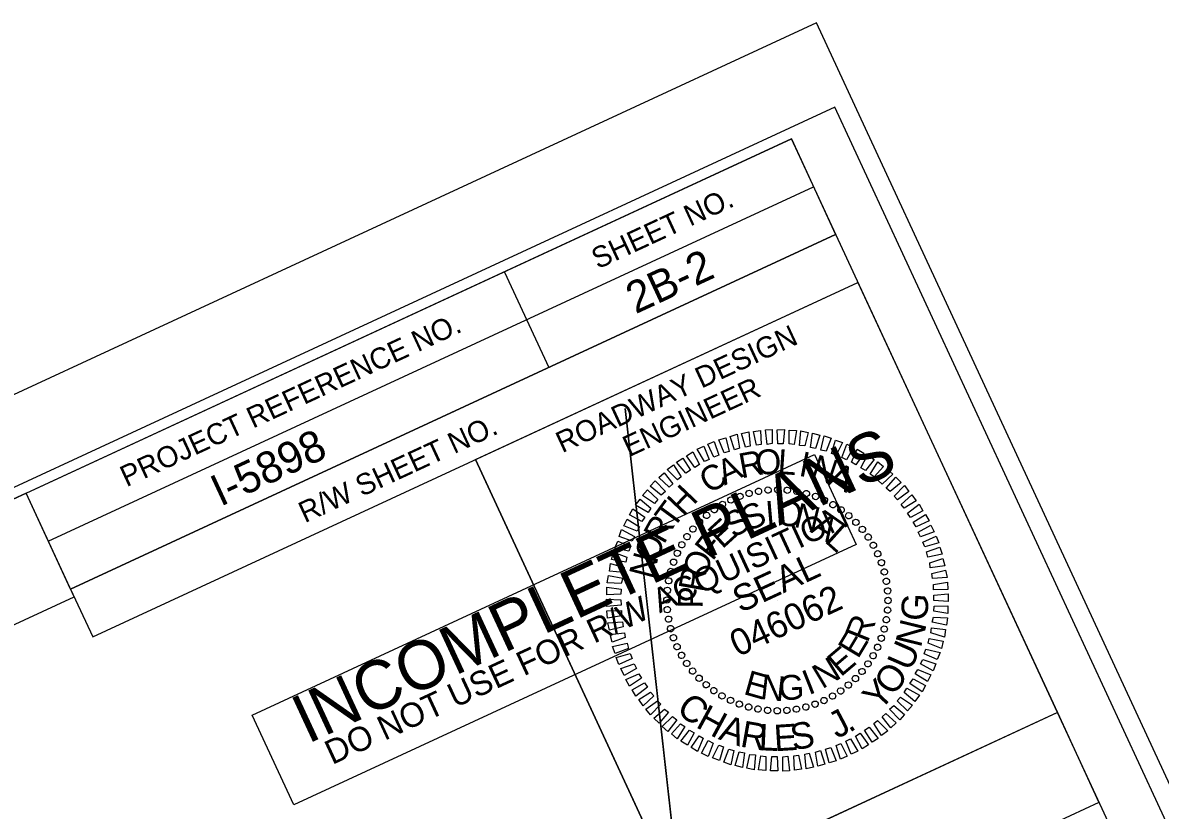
# Model space of a CAD drawing. Extents: x 1722892 to 1724880, y 971019 to 972720.
# Drawn here: x 1724231.4 to 1724501.2, y 972533.3 to 972720.2 of the extents above; entities that cross this region are included whole.
import ezdxf

# ---------------------------------------------------------------- set-up
doc = ezdxf.new("R2010")
doc.units = 0
for name, color, linetype in [('Default', 7, 'Continuous'), ('Old_Level_2', 7, 'Continuous'), ('Prop Dimension Text', 7, 'Continuous'), ('Sheet Data Field CELL', 7, 'Continuous'), ('Sheet Layout Plan Border', 7, 'Continuous'), ('Sheet Plan CELL', 7, 'Continuous'), ('Sheet Plot Border Inside CELL', 7, 'Continuous'), ('Sheet Plot Border Outside CELL', 7, 'Continuous'), ('Sheet Sticker Exception Certification CELL', 7, 'Continuous'), ('Sheet Sticker Incomplete CELL', 7, 'Continuous')]:
    doc.layers.add(name, color=color, linetype=linetype)

msp = doc.modelspace()

# ---------------------------------------------------------------- linework, layer by layer
at = {"layer": 'Old_Level_2'}
for p, q in [((1724401.55, 972607.86), (1724401.55, 972607.86)), ((1724403.73, 972608.52), (1724403.73, 972608.52)), ((1724405.91, 972609.05), (1724405.91, 972609.05)), ((1724408.21, 972609.35), (1724408.21, 972609.35)), ((1724410.5, 972609.42), (1724410.5, 972609.42)), ((1724412.79, 972609.36), (1724412.79, 972609.36)), ((1724415.06, 972609.01), (1724415.06, 972609.01)), ((1724417.32, 972608.54), (1724417.32, 972608.54)), ((1724419.46, 972607.83), (1724419.46, 972607.83)), ((1724395.48, 972604.69), (1724395.48, 972604.69)), ((1724397.36, 972605.95), (1724397.36, 972605.95)), ((1724399.41, 972607), (1724399.41, 972607)), ((1724421.63, 972606.96), (1724421.63, 972606.96)), ((1724423.6, 972605.89), (1724423.6, 972605.89)), ((1724425.55, 972604.62), (1724425.55, 972604.62)), ((1724393.59, 972603.31), (1724393.59, 972603.31)), ((1724427.38, 972603.25), (1724427.38, 972603.25)), ((1724390.37, 972600.12), (1724390.37, 972600.12)), ((1724391.89, 972601.78), (1724391.89, 972601.78)), ((1724429.04, 972601.73), (1724429.04, 972601.73)), ((1724430.57, 972600.03), (1724430.57, 972600.03)), ((1724388.99, 972598.29), (1724388.99, 972598.29)), ((1724431.95, 972598.14), (1724431.95, 972598.14)), ((1724386.65, 972594.37), (1724386.65, 972594.37)), ((1724387.73, 972596.34), (1724387.73, 972596.34)), ((1724433.21, 972596.25), (1724433.21, 972596.25)), ((1724434.26, 972594.2), (1724434.26, 972594.2)), ((1724385.78, 972592.2), (1724385.78, 972592.2)), ((1724435.12, 972592.07), (1724435.12, 972592.07)), ((1724385.08, 972590.06), (1724385.08, 972590.06)), ((1724435.78, 972589.88), (1724435.78, 972589.88)), ((1724384.61, 972587.8), (1724384.61, 972587.8)), ((1724436.31, 972587.7), (1724436.31, 972587.7)), ((1724384.2, 972583.24), (1724384.2, 972583.24)), ((1724384.25, 972585.53), (1724384.25, 972585.53)), ((1724410.44, 972583.18), (1724410.44, 972583.18)), ((1724436.61, 972585.41), (1724436.61, 972585.41)), ((1724436.68, 972583.11), (1724436.68, 972583.11)), ((1724384.26, 972580.95), (1724384.26, 972580.95)), ((1724436.62, 972580.82), (1724436.62, 972580.82)), ((1724384.56, 972578.65), (1724384.56, 972578.65)), ((1724436.27, 972578.56), (1724436.27, 972578.56)), ((1724385.1, 972576.47), (1724385.1, 972576.47)), ((1724435.8, 972576.3), (1724435.8, 972576.3)), ((1724385.75, 972574.29), (1724385.75, 972574.29)), ((1724386.61, 972572.15), (1724386.61, 972572.15)), ((1724435.09, 972574.15), (1724435.09, 972574.15)), ((1724387.66, 972570.1), (1724387.66, 972570.1)), ((1724433.15, 972570.01), (1724433.15, 972570.01)), ((1724434.22, 972571.99), (1724434.22, 972571.99)), ((1724388.93, 972568.22), (1724388.93, 972568.22)), ((1724431.88, 972568.07), (1724431.88, 972568.07)), ((1724390.31, 972566.33), (1724390.31, 972566.33)), ((1724391.83, 972564.63), (1724391.83, 972564.63)), ((1724428.99, 972564.57), (1724428.99, 972564.57)), ((1724430.51, 972566.23), (1724430.51, 972566.23)), ((1724393.49, 972563.11), (1724393.49, 972563.11)), ((1724395.33, 972561.73), (1724395.33, 972561.73)), ((1724425.4, 972561.67), (1724425.4, 972561.67)), ((1724427.29, 972563.05), (1724427.29, 972563.05)), ((1724397.27, 972560.47), (1724397.27, 972560.47)), ((1724399.25, 972559.39), (1724399.25, 972559.39)), ((1724421.47, 972559.35), (1724421.47, 972559.35)), ((1724423.51, 972560.4), (1724423.51, 972560.4)), ((1724401.41, 972558.52), (1724401.41, 972558.52)), ((1724403.56, 972557.82), (1724403.56, 972557.82)), ((1724405.82, 972557.35), (1724405.82, 972557.35)), ((1724408.08, 972556.99), (1724408.08, 972556.99)), ((1724410.37, 972556.94), (1724410.37, 972556.94)), ((1724412.67, 972557), (1724412.67, 972557)), ((1724414.96, 972557.3), (1724414.96, 972557.3)), ((1724417.14, 972557.84), (1724417.14, 972557.84)), ((1724419.33, 972558.49), (1724419.33, 972558.49))]:
    msp.add_line(p, q, dxfattribs=at)
for points in [[(1724405.44, 972619.98), (1724404.73, 972623.24), (1724406.42, 972623.47), (1724406.59, 972620.13)], [(1724407.97, 972620.16), (1724407.61, 972623.65), (1724409.2, 972623.72), (1724409.21, 972620.35)], [(1724410.52, 972620.29), (1724410.35, 972623.64), (1724412.12, 972623.68), (1724411.8, 972620.27)], [(1724413.21, 972620.26), (1724413.18, 972623.55), (1724414.97, 972623.44), (1724414.37, 972620.13)], [(1724415.66, 972619.88), (1724415.98, 972623.4), (1724417.68, 972623.01), (1724416.96, 972619.81)], [(1724395.37, 972617.13), (1724393.89, 972620.19), (1724395.46, 972620.89), (1724396.52, 972617.63)], [(1724397.79, 972618.13), (1724396.5, 972621.28), (1724398.19, 972621.75), (1724399.01, 972618.49)], [(1724400.23, 972618.85), (1724399.2, 972622.06), (1724400.86, 972622.58), (1724401.43, 972619.25)], [(1724402.88, 972619.49), (1724401.87, 972622.78), (1724403.65, 972623.18), (1724403.98, 972619.74)], [(1724418.27, 972619.4), (1724418.76, 972622.83), (1724420.48, 972622.39), (1724419.48, 972619.17)], [(1724420.76, 972618.81), (1724421.51, 972622.19), (1724423.18, 972621.61), (1724422, 972618.54)], [(1724423.26, 972617.98), (1724424.21, 972621.17), (1724425.88, 972620.59), (1724424.33, 972617.57)], [(1724390.85, 972614.71), (1724388.87, 972617.47), (1724390.38, 972618.43), (1724391.91, 972615.39)], [(1724393.09, 972616.08), (1724391.37, 972619.03), (1724392.95, 972619.73), (1724394.24, 972616.58)], [(1724425.72, 972617.09), (1724426.86, 972620.25), (1724428.47, 972619.46), (1724426.84, 972616.47)], [(1724428.03, 972615.94), (1724429.37, 972619.03), (1724430.93, 972618.1), (1724429.02, 972615.32)], [(1724386.72, 972611.72), (1724384.3, 972614.2), (1724385.74, 972615.31), (1724387.6, 972612.43)], [(1724388.73, 972613.33), (1724386.52, 972615.98), (1724388, 972616.87), (1724389.79, 972614.02)], [(1724430.18, 972614.6), (1724431.81, 972617.6), (1724433.39, 972616.62), (1724431.3, 972613.98)], [(1724432.41, 972613.12), (1724434.25, 972616.05), (1724435.57, 972614.89), (1724433.41, 972612.5)], [(1724384.76, 972610.01), (1724382.31, 972612.31), (1724383.56, 972613.44), (1724385.59, 972610.82)], [(1724434.33, 972611.56), (1724436.42, 972614.31), (1724437.77, 972613.1), (1724435.31, 972610.75)], [(1724382.82, 972608.14), (1724380.27, 972610.28), (1724381.41, 972611.52), (1724383.86, 972608.99)], [(1724436.25, 972609.76), (1724438.53, 972612.37), (1724439.75, 972611.16), (1724437.2, 972609)], [(1724438.1, 972607.86), (1724440.59, 972610.4), (1724441.62, 972608.99), (1724438.91, 972607.03)], [(1724381.23, 972606.15), (1724378.45, 972608.05), (1724379.58, 972609.42), (1724382.06, 972607.07)], [(1724439.76, 972605.88), (1724442.29, 972608.21), (1724443.35, 972606.75), (1724440.52, 972605.03)], [(1724378.25, 972601.86), (1724375.35, 972603.41), (1724376.14, 972604.9), (1724379.01, 972602.92)], [(1724379.75, 972604.04), (1724376.78, 972605.73), (1724377.87, 972607.19), (1724380.37, 972605.04)], [(1724441.28, 972603.82), (1724444.02, 972605.97), (1724444.93, 972604.43), (1724442.01, 972602.79)], [(1724377.15, 972599.58), (1724374.03, 972600.86), (1724374.82, 972602.46), (1724377.75, 972600.62)], [(1724442.66, 972601.7), (1724445.53, 972603.56), (1724446.4, 972602.01), (1724443.3, 972600.62)], [(1724375.97, 972597.21), (1724372.9, 972598.27), (1724373.48, 972599.95), (1724376.55, 972598.3)], [(1724443.84, 972599.37), (1724446.83, 972601), (1724447.61, 972599.4), (1724444.39, 972598.24)], [(1724375.22, 972594.81), (1724371.89, 972595.57), (1724372.54, 972597.23), (1724375.61, 972595.93)], [(1724444.94, 972597), (1724448.04, 972598.39), (1724448.7, 972596.79), (1724445.39, 972595.82)], [(1724374.44, 972592.22), (1724371.1, 972592.87), (1724371.55, 972594.6), (1724374.69, 972593.39)], [(1724445.8, 972594.63), (1724448.94, 972595.8), (1724449.53, 972594.11), (1724446.11, 972593.38)], [(1724373.9, 972589.75), (1724370.58, 972590.12), (1724370.81, 972591.92), (1724374.07, 972590.94)], [(1724446.58, 972592.04), (1724449.68, 972593.08), (1724450.13, 972591.32), (1724446.69, 972590.87)], [(1724373.4, 972587.18), (1724370.08, 972587.32), (1724370.38, 972589.09), (1724373.74, 972588.4)], [(1724447.07, 972589.49), (1724450.28, 972590.29), (1724450.7, 972588.58), (1724447.17, 972588.32)], [(1724373.25, 972584.61), (1724370, 972584.49), (1724369.99, 972586.29), (1724373.38, 972585.78)], [(1724447.46, 972586.89), (1724450.78, 972587.46), (1724450.88, 972585.7), (1724447.42, 972585.65)], [(1724373.36, 972581.99), (1724369.91, 972581.66), (1724369.91, 972583.46), (1724373.32, 972583.26)], [(1724447.52, 972584.36), (1724450.96, 972584.69), (1724450.96, 972582.89), (1724447.55, 972583.1)], [(1724373.42, 972579.47), (1724370.09, 972578.9), (1724370, 972580.65), (1724373.46, 972580.71)], [(1724447.63, 972581.74), (1724450.88, 972581.86), (1724450.88, 972580.06), (1724447.5, 972580.57)], [(1724373.81, 972576.87), (1724370.59, 972576.06), (1724370.17, 972577.78), (1724373.71, 972578.04)], [(1724447.48, 972579.17), (1724450.8, 972579.04), (1724450.5, 972577.26), (1724447.14, 972577.96)], [(1724374.29, 972574.31), (1724371.19, 972573.27), (1724370.75, 972575.03), (1724374.19, 972575.48)], [(1724446.98, 972576.6), (1724450.3, 972576.24), (1724450.06, 972574.44), (1724446.8, 972575.41)], [(1724375.08, 972571.73), (1724371.93, 972570.55), (1724371.34, 972572.24), (1724374.77, 972572.97)], [(1724446.43, 972574.13), (1724449.77, 972573.48), (1724449.33, 972571.76), (1724446.19, 972572.97)], [(1724375.94, 972569.36), (1724372.83, 972567.97), (1724372.18, 972569.57), (1724375.48, 972570.53)], [(1724445.65, 972571.55), (1724448.99, 972570.78), (1724448.34, 972569.13), (1724445.27, 972570.43)], [(1724377.03, 972566.98), (1724374.04, 972565.36), (1724373.27, 972566.96), (1724376.48, 972568.11)], [(1724443.73, 972566.77), (1724446.84, 972565.5), (1724446.05, 972563.89), (1724443.13, 972565.73)], [(1724444.9, 972569.15), (1724447.97, 972568.08), (1724447.39, 972566.4), (1724444.33, 972568.05)], [(1724378.22, 972564.65), (1724375.34, 972562.79), (1724374.47, 972564.35), (1724377.58, 972565.73)], [(1724442.62, 972564.5), (1724445.53, 972562.94), (1724444.74, 972561.45), (1724441.86, 972563.43)], [(1724379.6, 972562.53), (1724376.86, 972560.39), (1724375.94, 972561.92), (1724378.86, 972563.57)], [(1724441.12, 972562.32), (1724444.09, 972560.62), (1724443, 972559.16), (1724440.5, 972561.32)], [(1724381.11, 972560.48), (1724378.58, 972558.15), (1724377.53, 972559.61), (1724380.35, 972561.33)], [(1724382.77, 972558.49), (1724380.29, 972555.95), (1724379.25, 972557.37), (1724381.97, 972559.32)], [(1724439.65, 972560.21), (1724442.43, 972558.3), (1724441.29, 972556.94), (1724438.82, 972559.28)], [(1724384.62, 972556.6), (1724382.35, 972553.98), (1724381.12, 972555.19), (1724383.67, 972557.36)], [(1724436.11, 972556.34), (1724438.57, 972554.05), (1724437.31, 972552.92), (1724435.29, 972555.54)], [(1724438.06, 972558.21), (1724440.6, 972556.08), (1724439.46, 972554.83), (1724437.02, 972557.36)], [(1724386.54, 972554.8), (1724384.45, 972552.04), (1724383.11, 972553.25), (1724385.57, 972555.6)], [(1724388.46, 972553.23), (1724386.63, 972550.31), (1724385.31, 972551.47), (1724387.47, 972553.85)], [(1724434.15, 972554.64), (1724436.58, 972552.15), (1724435.14, 972551.05), (1724433.28, 972553.92)], [(1724390.69, 972551.75), (1724389.06, 972548.76), (1724387.49, 972549.73), (1724389.58, 972552.38)], [(1724392.85, 972550.42), (1724391.5, 972547.32), (1724389.95, 972548.25), (1724391.85, 972551.04)], [(1724430.02, 972551.65), (1724432, 972548.89), (1724430.49, 972547.92), (1724428.96, 972550.96)], [(1724432.15, 972553.02), (1724434.36, 972550.38), (1724432.87, 972549.48), (1724431.08, 972552.34)], [(1724395.15, 972549.27), (1724394.01, 972546.1), (1724392.41, 972546.89), (1724394.03, 972549.89)], [(1724397.62, 972548.37), (1724396.67, 972545.18), (1724394.99, 972545.76), (1724396.55, 972548.78)], [(1724423.08, 972548.22), (1724424.38, 972545.08), (1724422.69, 972544.6), (1724421.86, 972547.87)], [(1724425.5, 972549.22), (1724426.99, 972546.17), (1724425.41, 972545.46), (1724424.35, 972548.72)], [(1724427.79, 972550.27), (1724429.5, 972547.33), (1724427.93, 972546.62), (1724426.63, 972549.77)], [(1724400.11, 972547.55), (1724399.37, 972544.16), (1724397.69, 972544.75), (1724398.87, 972547.82)], [(1724402.61, 972546.95), (1724402.12, 972543.52), (1724400.39, 972543.96), (1724401.39, 972547.18)], [(1724405.22, 972546.48), (1724404.89, 972542.95), (1724403.19, 972543.35), (1724403.91, 972546.54)], [(1724407.67, 972546.1), (1724407.7, 972542.8), (1724405.9, 972542.92), (1724406.5, 972546.23)], [(1724410.36, 972546.06), (1724410.53, 972542.72), (1724408.75, 972542.67), (1724409.07, 972546.08)], [(1724412.91, 972546.2), (1724413.26, 972542.71), (1724411.67, 972542.63), (1724411.67, 972546)], [(1724415.44, 972546.38), (1724416.15, 972543.12), (1724414.46, 972542.88), (1724414.29, 972546.23)], [(1724417.99, 972546.86), (1724419, 972543.57), (1724417.22, 972543.17), (1724416.89, 972546.62)], [(1724420.64, 972547.51), (1724421.68, 972544.29), (1724420.01, 972543.77), (1724419.44, 972547.1)]]:
    msp.add_lwpolyline(points, close=True, dxfattribs=at)
for centre, major_axis in [((1724408.21, 972609.31), (-0.064, 0.75)), ((1724410.5, 972609.4), (0.002, 0.753)), ((1724412.78, 972609.3), (0.067, 0.75)), ((1724399.41, 972606.97), (-0.317, 0.683)), ((1724401.52, 972607.84), (-0.256, 0.708)), ((1724403.71, 972608.53), (-0.193, 0.728)), ((1724405.94, 972609.02), (-0.129, 0.742)), ((1724415.05, 972609), (0.132, 0.741)), ((1724417.28, 972608.5), (0.197, 0.727)), ((1724419.47, 972607.8), (0.259, 0.707)), ((1724421.58, 972606.92), (0.32, 0.682)), ((1724395.44, 972604.7), (-0.43, 0.618)), ((1724397.38, 972605.92), (-0.375, 0.653)), ((1724423.6, 972605.86), (0.378, 0.651)), ((1724425.53, 972604.63), (0.433, 0.616)), ((1724391.93, 972601.77), (-0.531, 0.534)), ((1724393.63, 972603.31), (-0.483, 0.578)), ((1724427.34, 972603.23), (0.485, 0.576)), ((1724429.03, 972601.68), (0.534, 0.531)), ((1724388.99, 972598.27), (-0.616, 0.433)), ((1724390.39, 972600.08), (-0.576, 0.485)), ((1724430.57, 972599.99), (0.578, 0.483)), ((1724387.75, 972596.34), (-0.651, 0.378)), ((1724431.96, 972598.17), (0.618, 0.43)), ((1724433.18, 972596.24), (0.653, 0.375)), ((1724386.69, 972594.32), (-0.682, 0.32)), ((1724434.23, 972594.21), (0.683, 0.317)), ((1724385.81, 972592.21), (-0.707, 0.259)), ((1724435.1, 972592.09), (0.708, 0.256)), ((1724384.62, 972587.79), (-0.741, 0.132)), ((1724385.12, 972590.02), (-0.727, 0.197)), ((1724435.79, 972589.91), (0.728, 0.193)), ((1724436.28, 972587.67), (0.742, 0.129)), ((1724384.31, 972585.52), (-0.75, 0.067)), ((1724436.57, 972585.4), (0.75, 0.064)), ((1724384.21, 972583.24), (-0.753, 0.002)), ((1724436.67, 972583.12), (0.753, -0.002)), ((1724384.3, 972580.95), (-0.75, -0.064)), ((1724436.56, 972580.83), (0.75, -0.067)), ((1724384.6, 972578.68), (-0.742, -0.129)), ((1724436.26, 972578.56), (0.741, -0.132)), ((1724385.09, 972576.45), (-0.728, -0.193)), ((1724385.77, 972574.26), (-0.708, -0.256)), ((1724435.06, 972574.15), (0.707, -0.259)), ((1724435.76, 972576.33), (0.727, -0.197)), ((1724386.64, 972572.15), (-0.683, -0.317)), ((1724434.18, 972572.04), (0.682, -0.32)), ((1724387.69, 972570.12), (-0.653, -0.375)), ((1724433.12, 972570.01), (0.651, -0.378)), ((1724388.92, 972568.18), (-0.618, -0.43)), ((1724390.31, 972566.37), (-0.578, -0.483)), ((1724430.49, 972566.27), (0.576, -0.485)), ((1724431.89, 972568.08), (0.616, -0.433)), ((1724391.85, 972564.67), (-0.534, -0.531)), ((1724428.94, 972564.59), (0.531, -0.534)), ((1724393.53, 972563.12), (-0.485, -0.576)), ((1724395.34, 972561.73), (-0.433, -0.616)), ((1724397.27, 972560.49), (-0.378, -0.651)), ((1724425.43, 972561.66), (0.43, -0.618)), ((1724427.25, 972563.05), (0.483, -0.578)), ((1724399.3, 972559.43), (-0.32, -0.682)), ((1724401.41, 972558.55), (-0.259, -0.707)), ((1724403.59, 972557.86), (-0.197, -0.727)), ((1724417.17, 972557.83), (0.193, -0.728)), ((1724419.35, 972558.51), (0.256, -0.708)), ((1724421.47, 972559.38), (0.317, -0.683)), ((1724423.5, 972560.43), (0.375, -0.653)), ((1724405.82, 972557.36), (-0.132, -0.741)), ((1724408.09, 972557.05), (-0.067, -0.75)), ((1724410.38, 972556.95), (-0.002, -0.753)), ((1724412.66, 972557.04), (0.064, -0.75)), ((1724414.93, 972557.34), (0.129, -0.742))]:
    msp.add_ellipse(centre, major_axis=major_axis, ratio=0.999708, dxfattribs=at)
at = {"layer": 'Prop Dimension Text'}
msp.add_lwpolyline([(1724107.47, 972520.92), (1724243.59, 972584.01), (1724232.21, 972608.57), (1724096.09, 972545.49)], close=True, dxfattribs=at)
at = {"layer": 'Sheet Layout Plan Border'}
msp.add_lwpolyline([(1724374.31, 972628.66), (1724393.21, 972460.35), (1724068.11, 972404.72), (1724049.69, 972271.07), (1723832.27, 972270.2), (1723815.72, 972244.69), (1723599.72, 972315.43), (1723098.13, 972082.96), (1723600.74, 971158.62), (1723483.33, 971374.55), (1723802.12, 971464.67), (1724031.92, 971474.7), (1724072.16, 971562.21), (1724326.28, 971494.87), (1724493, 971572.14)], close=True, dxfattribs=at)
at = {"layer": 'Sheet Plan CELL'}
for p, q in [((1724237.48, 972597.18), (1724418.99, 972681.29)), ((1724242.76, 972585.81), (1724424.24, 972669.95)), ((1724242.76, 972585.81), (1724424.24, 972669.95)), ((1724248.01, 972574.48), (1724429.5, 972658.61)), ((1724345.66, 972661.07), (1724356.22, 972638.41)), ((1724338.78, 972616.55), (1724386.09, 972514.52)), ((1724242.76, 972585.81), (1724248.01, 972574.48))]:
    msp.add_line(p, q, dxfattribs=at)
for points in [[(1724413.74, 972692.69), (1723052.76, 972061.94), (1723494.28, 971109.28), (1724855.24, 971740.02)], [(1724232.21, 972608.57), (1724413.74, 972692.69), (1724424.24, 972669.95), (1724242.76, 972585.81)], [(1724338.78, 972616.55), (1724429.5, 972658.61), (1724476.82, 972556.53), (1724386.1, 972514.47)]]:
    msp.add_lwpolyline(points, close=True, dxfattribs=at)
at = {"layer": 'Sheet Plot Border Inside CELL'}
msp.add_lwpolyline([(1723356.08, 971042.46), (1724867.62, 971743), (1724424.02, 972700.19), (1722912.46, 971999.66)], close=True, dxfattribs=at)
at = {"layer": 'Sheet Plot Border Outside CELL'}
msp.add_lwpolyline([(1723352.69, 971018.84), (1724880.13, 971726.74), (1724419.69, 972720.23), (1722892.25, 972012.33)], close=True, dxfattribs=at)
at = {"layer": 'Sheet Sticker Exception Certification CELL'}
for p, q in [((1724295.32, 972472.43), (1724476.81, 972556.54)), ((1724476.82, 972556.53), (1724486.7, 972535.21)), ((1724486.7, 972535.22), (1724305.2, 972451.11))]:
    msp.add_line(p, q, dxfattribs=at)
at = {"layer": 'Sheet Sticker Incomplete CELL'}
msp.add_lwpolyline([(1724295.75, 972534.61), (1724285.87, 972555.93), (1724419.24, 972617.74), (1724429.12, 972596.42)], close=True, dxfattribs=at)

# ---------------------------------------------------------------- texts
at = {"layer": 'Default'}
for s, rotation, p in [('G', 86.6654, (1724445.96, 972578.15)), ('N', 76.0944, (1724444.43, 972571.72)), ('U', 66.3003, (1724441.99, 972566.11)), ('O', 54.9069, (1724438, 972560.21)), ('Y', 47.1082, (1724434.63, 972556.69)), ('C', 322.0655, (1724386.16, 972556.79)), ('H', 331.5092, (1724390.82, 972553.16)), ('J', 27.8977, (1724424.57, 972550.21)), ('A', 341.349, (1724396.23, 972550.25)), ('R', 350.0617, (1724401.38, 972548.48)), ('L', 357.4339, (1724405.91, 972547.6)), ('E', 3.6181, (1724409.77, 972547.32)), ('S', 10.6247, (1724414.15, 972547.5)), ('.', 33.0796, (1724427.49, 972551.62))]:
    msp.add_text(s, height=6.27, rotation=rotation, dxfattribs=at).set_placement(p)
at = {"layer": 'Old_Level_2'}
for s, height, rotation, p in [('R', 5.9, 10.4867, (1724401.88, 972612.09)), ('O', 5.9, 3.2868, (1724405.37, 972612.92)), ('L', 5.9, 356.0865, (1724410.36, 972613.18)), ('I', 5.9, 348.8857, (1724415.27, 972612.77)), ('C', 5.9, 32.0855, (1724394.26, 972608.28)), ('A', 5.9, 24.8859, (1724397.84, 972610.36)), ('N', 5.9, 341.6845, (1724418, 972612.29)), ('A', 5.9, 334.4828, (1724422.12, 972610.86)), ('H', 5.9, 46.4851, (1724388.02, 972602.93)), ('T', 5.9, 53.6854, (1724385.71, 972599.9)), ('S', 5.9, 33.1212, (1724400.12, 972597.76)), ('S', 5.9, 23.766, (1724403.48, 972599.44)), ('I', 5.9, 5.0552, (1724407.85, 972600.75)), ('O', 5.9, 355.6991, (1724410.05, 972601)), ('N', 5.9, 346.3422, (1724414.11, 972600.65)), ('R', 5.9, 60.8861, (1724383.52, 972596.27)), ('E', 5.9, 42.4767, (1724397.35, 972595.19)), ('A', 5.9, 327.6259, (1724417.98, 972599.5)), ('F', 5.9, 51.8326, (1724395.02, 972592.32)), ('L', 5.9, 318.2665, (1724421.39, 972597.14)), ('O', 5.9, 68.0873, (1724381.68, 972591.78)), ('N', 5.9, 75.2891, (1724380.84, 972588)), ('O', 5.9, 70.5468, (1724393.26, 972588.04)), ('SEAL', 6.273, 24.8656, (1724401.65, 972580.08)), ('R', 5.9, 79.9053, (1724392.73, 972584.94)), ('P', 5.9, 89.2645, (1724392.69, 972581.2)), ('046062', 6.275, 24.8656, (1724401.01, 972569.64)), ('R', 5.9, 68.347, (1724431.8, 972572.91)), ('E', 5.9, 58.9897, (1724429.53, 972569.08)), ('E', 5.9, 40.2774, (1724425.44, 972564.82)), ('N', 5.9, 30.922, (1724421.05, 972562)), ('E', 5.9, 344.1425, (1724402.14, 972560.97)), ('N', 5.9, 353.4996, (1724406.2, 972559.8)), ('G', 5.9, 2.8558, (1724410.8, 972559.41)), ('I', 5.9, 21.5668, (1724417.83, 972560.61))]:
    msp.add_text(s, height=height, rotation=rotation, dxfattribs=at).set_placement(p)
at = {"layer": 'Sheet Data Field CELL'}
for s, p in [('2B-2', (1724376.77, 972651.03)), ('  I-5898 ', (1724273.25, 972602.99))]:
    msp.add_text(s, height=7.5, rotation=24.8656, dxfattribs=at).set_placement(p)
at = {"layer": 'Sheet Plan CELL'}
for s, height, p in [('SHEET NO.', 5, (1724367.81, 972661.68)), ('PROJECT REFERENCE NO.', 5.0001, (1724256.02, 972609.99)), ('ROADWAY DESIGN', 5.0001, (1724359.37, 972618.06)), ('ENGINEER', 5, (1724375.23, 972617.1)), ('R/W SHEET NO.', 5.0001, (1724298.34, 972601.44))]:
    msp.add_text(s, height=height, rotation=24.8656, dxfattribs=at).set_placement(p)
at = {"layer": 'Sheet Sticker Incomplete CELL'}
for s, height, p in [('INCOMPLETE PLANS', 11.52, (1724298.95, 972548.99)), ('DO NOT USE FOR R/W ACQUISITION', 5.76, (1724304.82, 972544.05))]:
    msp.add_text(s, height=height, rotation=24.8656, dxfattribs=at).set_placement(p)

doc.saveas('drawing.dxf')
